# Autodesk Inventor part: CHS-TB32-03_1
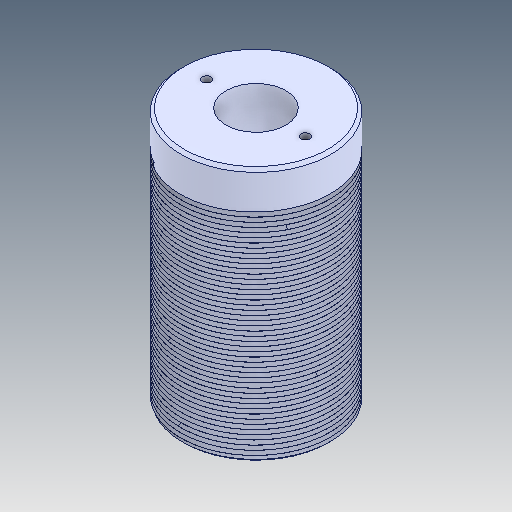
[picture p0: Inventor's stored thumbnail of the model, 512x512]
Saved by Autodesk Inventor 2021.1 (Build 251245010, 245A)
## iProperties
Created: 2021-05
Part Number: CHS-TB32-03_1
Material: Ogólny
Document SubType Name: Modeling
Designer: user
Density: 1 g/cm^3
Appearance: Domyślna
Author: user
Revision Number: ÈÎºÎ
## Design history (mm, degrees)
feature "Í¹Ì¨-À­Éì1"
node "Bryła1"
